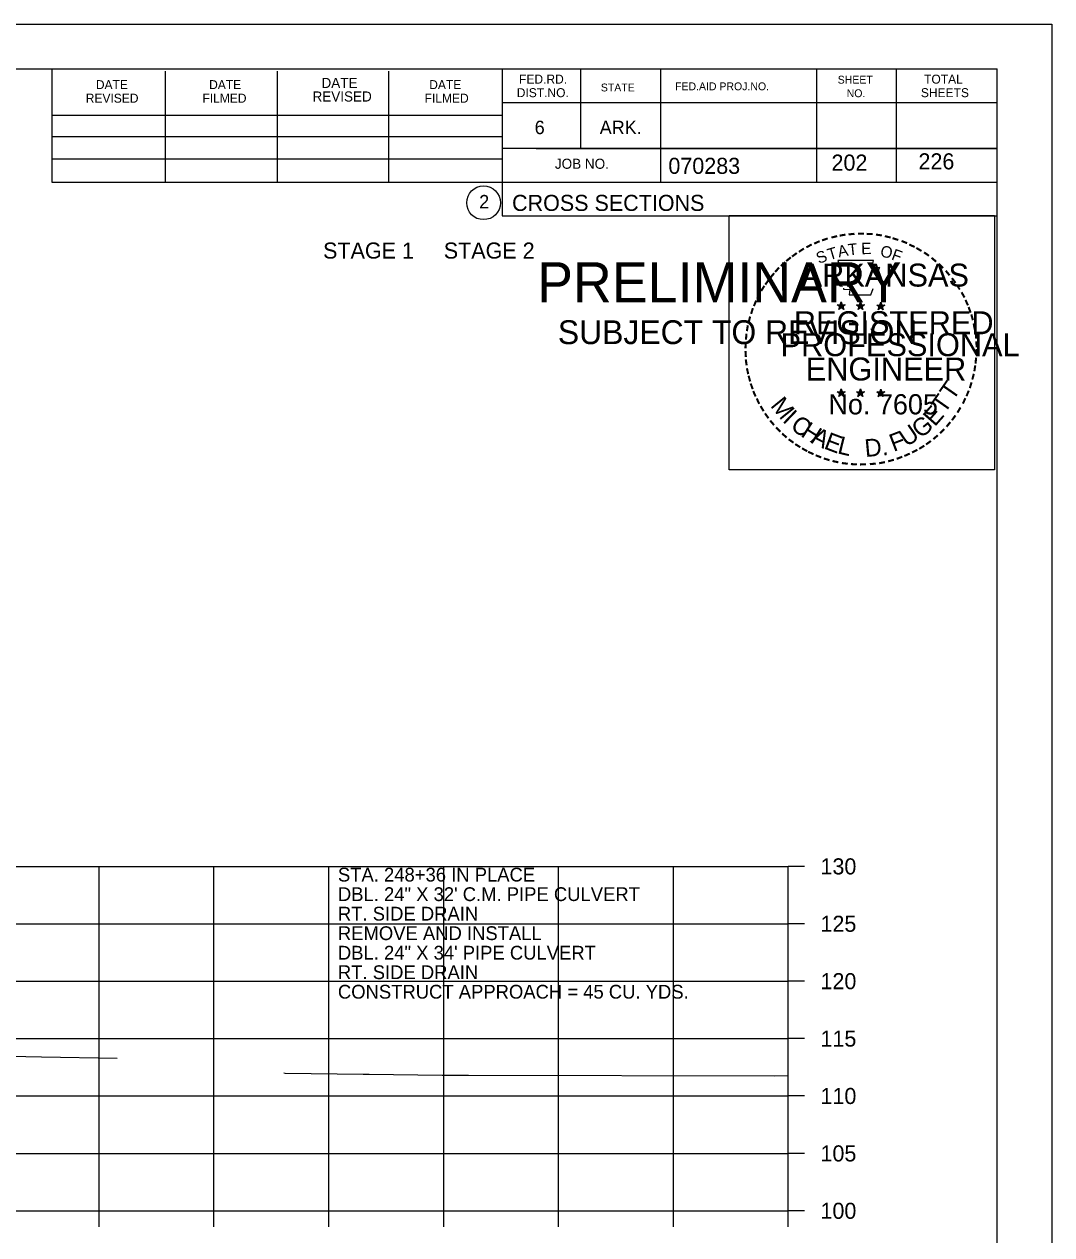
# Model space of a CAD drawing. Extents: x 1175611 to 1176402, y -433344 to -416213.
# Drawn here: x 1175854.5 to 1175943.9, y -421502 to -421396.6 of the extents above; entities that cross this region are included whole.
import ezdxf

# ---------------------------------------------------------------- set-up
doc = ezdxf.new("R2010")
doc.units = 0
for name, color, linetype in [('Default', 7, 'Continuous'), ('R_Axis', 7, 'Continuous'), ('R_Axis Annot', 7, 'Continuous'), ('R_Border', 7, 'Continuous'), ('R_Border Notes', 7, 'Continuous'), ('R_Border PE', 7, 'Continuous'), ('R_Border Prem', 7, 'Continuous'), ('R_Exist Surface', 7, 'Continuous'), ('R_Grid', 7, 'Continuous'), ('R_No Plot', 7, 'Continuous'), ('R_Water Annot', 7, 'Continuous')]:
    doc.layers.add(name, color=color, linetype=linetype)

msp = doc.modelspace()

# ---------------------------------------------------------------- linework, layer by layer
at = {"layer": 'R_Axis'}
for p, q in [((1175920.97, -421499.96), (1175920.97, -421469.96)), ((1175922.37, -421469.96), (1175920.97, -421469.96)), ((1175922.37, -421474.96), (1175920.97, -421474.96)), ((1175922.37, -421479.96), (1175920.97, -421479.96)), ((1175922.37, -421484.96), (1175920.97, -421484.96)), ((1175922.37, -421489.96), (1175920.97, -421489.96)), ((1175922.37, -421494.96), (1175920.97, -421494.96)), ((1175640.97, -421499.96), (1175920.97, -421499.96)), ((1175860.97, -421501.36), (1175860.97, -421499.96)), ((1175870.97, -421501.36), (1175870.97, -421499.96)), ((1175880.97, -421501.36), (1175880.97, -421499.96)), ((1175890.97, -421501.36), (1175890.97, -421499.96)), ((1175900.97, -421501.36), (1175900.97, -421499.96)), ((1175910.97, -421501.36), (1175910.97, -421499.96)), ((1175920.97, -421501.36), (1175920.97, -421499.96)), ((1175922.37, -421499.96), (1175920.97, -421499.96))]:
    msp.add_line(p, q, dxfattribs=at)
at = {"layer": 'R_Border'}
for p, q in [((1175622.97, -421400.5), (1175939.15, -421400.5)), ((1175856.89, -421410.38), (1175856.89, -421400.5)), ((1175866.75, -421410.38), (1175866.75, -421400.7)), ((1175876.51, -421410.38), (1175876.51, -421400.7)), ((1175886.19, -421410.38), (1175886.19, -421400.7)), ((1175896.05, -421400.5), (1175896.05, -421413.3)), ((1175902.89, -421400.5), (1175902.89, -421407.44)), ((1175909.83, -421400.5), (1175909.83, -421410.38)), ((1175923.41, -421400.5), (1175923.41, -421410.38)), ((1175930.35, -421400.5), (1175930.35, -421410.38)), ((1175939.15, -421605.96), (1175939.15, -421400.5)), ((1175939.15, -421403.44), (1175896.05, -421403.44)), ((1175939.15, -421403.42), (1175939.15, -421403.42)), ((1175856.89, -421404.52), (1175896.05, -421404.52)), ((1175856.89, -421406.38), (1175896.05, -421406.38)), ((1175939.15, -421407.44), (1175896.05, -421407.44)), ((1175899.01, -421407.44), (1175939.15, -421407.44)), ((1175856.89, -421410.38), (1175856.89, -421408.32)), ((1175856.89, -421408.32), (1175896.05, -421408.32)), ((1175939.15, -421410.38), (1175856.89, -421410.38)), ((1175896.05, -421413.3), (1175939.15, -421413.3))]:
    msp.add_line(p, q, dxfattribs=at)
msp.add_circle((1175894.44, -421412.16), 1.47, dxfattribs=at)
at = {"layer": 'R_Border PE'}
for p, q in [((1175925.23, -421421.05), (1175925.58, -421421.16)), ((1175925.23, -421421.05), (1175925.49, -421421.1)), ((1175925.23, -421421.05), (1175925.47, -421421.18)), ((1175925.37, -421421.46), (1175925.58, -421421.16)), ((1175925.37, -421421.46), (1175925.49, -421421.22)), ((1175925.37, -421421.46), (1175925.58, -421421.24)), ((1175925.58, -421420.8), (1175925.54, -421421.05)), ((1175925.58, -421421.16), (1175925.58, -421420.8)), ((1175925.58, -421420.8), (1175925.63, -421421.05)), ((1175925.93, -421421.05), (1175925.58, -421421.16)), ((1175925.8, -421421.46), (1175925.58, -421421.16)), ((1175925.8, -421421.46), (1175925.58, -421421.25)), ((1175925.93, -421421.05), (1175925.64, -421421.1)), ((1175925.8, -421421.46), (1175925.66, -421421.17)), ((1175925.93, -421421.05), (1175925.73, -421421.16)), ((1175926.9, -421421.05), (1175927.25, -421421.16)), ((1175926.9, -421421.05), (1175927.16, -421421.1)), ((1175926.9, -421421.05), (1175927.14, -421421.18)), ((1175927.04, -421421.46), (1175927.25, -421421.16)), ((1175927.04, -421421.46), (1175927.16, -421421.22)), ((1175927.04, -421421.46), (1175927.25, -421421.24)), ((1175927.25, -421420.8), (1175927.21, -421421.05)), ((1175927.25, -421421.16), (1175927.25, -421420.8)), ((1175927.25, -421420.8), (1175927.3, -421421.05)), ((1175927.6, -421421.05), (1175927.25, -421421.16)), ((1175927.47, -421421.46), (1175927.25, -421421.16)), ((1175927.47, -421421.46), (1175927.25, -421421.25)), ((1175927.6, -421421.05), (1175927.31, -421421.1)), ((1175927.47, -421421.46), (1175927.33, -421421.17)), ((1175927.6, -421421.05), (1175927.4, -421421.16)), ((1175928.67, -421421.07), (1175929.02, -421421.18)), ((1175928.67, -421421.07), (1175928.92, -421421.11)), ((1175928.67, -421421.07), (1175928.91, -421421.19)), ((1175928.8, -421421.47), (1175929.02, -421421.18)), ((1175928.8, -421421.47), (1175928.93, -421421.23)), ((1175928.8, -421421.47), (1175929.02, -421421.26)), ((1175929.02, -421420.81), (1175928.98, -421421.06)), ((1175929.02, -421421.18), (1175929.02, -421420.81)), ((1175929.02, -421420.81), (1175929.07, -421421.06)), ((1175929.36, -421421.07), (1175929.02, -421421.18)), ((1175929.23, -421421.47), (1175929.02, -421421.18)), ((1175929.23, -421421.47), (1175929.02, -421421.26)), ((1175929.36, -421421.07), (1175929.08, -421421.11)), ((1175929.23, -421421.47), (1175929.09, -421421.18)), ((1175929.36, -421421.07), (1175929.16, -421421.17)), ((1175925.23, -421428.63), (1175925.58, -421428.74)), ((1175925.23, -421428.63), (1175925.48, -421428.67)), ((1175925.23, -421428.63), (1175925.47, -421428.75)), ((1175925.36, -421429.03), (1175925.58, -421428.74)), ((1175925.36, -421429.03), (1175925.49, -421428.79)), ((1175925.36, -421429.03), (1175925.58, -421428.82)), ((1175925.58, -421428.37), (1175925.54, -421428.62)), ((1175925.58, -421428.74), (1175925.58, -421428.37)), ((1175925.58, -421428.37), (1175925.63, -421428.62)), ((1175925.93, -421428.63), (1175925.58, -421428.74)), ((1175925.79, -421429.03), (1175925.58, -421428.74)), ((1175925.79, -421429.03), (1175925.58, -421428.82)), ((1175925.93, -421428.63), (1175925.64, -421428.68)), ((1175925.79, -421429.03), (1175925.66, -421428.74)), ((1175925.93, -421428.63), (1175925.72, -421428.73)), ((1175926.9, -421428.63), (1175927.25, -421428.74)), ((1175926.9, -421428.63), (1175927.15, -421428.67)), ((1175926.9, -421428.63), (1175927.14, -421428.75)), ((1175927.03, -421429.03), (1175927.25, -421428.74)), ((1175927.03, -421429.03), (1175927.16, -421428.79)), ((1175927.03, -421429.03), (1175927.25, -421428.82)), ((1175927.25, -421428.37), (1175927.21, -421428.62)), ((1175927.25, -421428.74), (1175927.25, -421428.37)), ((1175927.25, -421428.37), (1175927.3, -421428.62)), ((1175927.6, -421428.63), (1175927.25, -421428.74)), ((1175927.46, -421429.03), (1175927.25, -421428.74)), ((1175927.46, -421429.03), (1175927.25, -421428.82)), ((1175927.6, -421428.63), (1175927.31, -421428.68)), ((1175927.46, -421429.03), (1175927.32, -421428.74)), ((1175927.6, -421428.63), (1175927.39, -421428.73)), ((1175928.67, -421428.64), (1175929.02, -421428.75)), ((1175928.67, -421428.64), (1175928.92, -421428.68)), ((1175928.67, -421428.64), (1175928.9, -421428.76)), ((1175928.8, -421429.04), (1175929.02, -421428.75)), ((1175928.8, -421429.04), (1175928.93, -421428.8)), ((1175928.8, -421429.04), (1175929.01, -421428.83)), ((1175929.02, -421428.38), (1175928.97, -421428.63)), ((1175929.23, -421429.04), (1175929.01, -421428.83)), ((1175929.02, -421428.75), (1175929.02, -421428.38)), ((1175929.02, -421428.38), (1175929.06, -421428.63)), ((1175929.36, -421428.64), (1175929.02, -421428.75)), ((1175929.23, -421429.04), (1175929.02, -421428.75)), ((1175929.36, -421428.64), (1175929.08, -421428.69)), ((1175929.23, -421429.04), (1175929.09, -421428.75)), ((1175929.36, -421428.64), (1175929.16, -421428.74))]:
    msp.add_line(p, q, dxfattribs=at)
for points in [[(1175925.28, -421417.18), (1175925.54, -421418)], [(1175928.79, -421418.1), (1175928.93, -421417.81), (1175928.24, -421417.84), (1175928.39, -421417.18), (1175925.28, -421417.18)], [(1175925.77, -421419.6), (1175925.77, -421419.69), (1175926.33, -421419.7), (1175926.28, -421420.18), (1175928.15, -421420.18), (1175928.35, -421419.64)], [(1175925.58, -421420.8), (1175925.8, -421421.46), (1175925.23, -421421.05), (1175925.93, -421421.05), (1175925.37, -421421.46), (1175925.58, -421420.8)], [(1175927.25, -421420.8), (1175927.47, -421421.46), (1175926.9, -421421.05), (1175927.6, -421421.05), (1175927.04, -421421.46), (1175927.25, -421420.8)], [(1175929.02, -421420.81), (1175929.23, -421421.47), (1175928.67, -421421.07), (1175929.36, -421421.07), (1175928.8, -421421.47), (1175929.02, -421420.81)], [(1175925.58, -421428.37), (1175925.79, -421429.03), (1175925.23, -421428.63), (1175925.93, -421428.63), (1175925.36, -421429.03), (1175925.58, -421428.37)], [(1175927.25, -421428.37), (1175927.46, -421429.03), (1175926.9, -421428.63), (1175927.6, -421428.63), (1175927.03, -421429.03), (1175927.25, -421428.37)], [(1175929.02, -421428.38), (1175929.23, -421429.04), (1175928.67, -421428.64), (1175929.36, -421428.64), (1175928.8, -421429.04), (1175929.02, -421428.38)]]:
    msp.add_lwpolyline(points, dxfattribs=at)
for centre, radius in [((1175925.58, -421421.17), 0.172), ((1175925.58, -421421.17), 0.145), ((1175925.58, -421421.17), 0.116), ((1175925.58, -421421.17), 0.0991), ((1175925.58, -421421.17), 0.0747), ((1175925.58, -421421.17), 0.0495), ((1175925.58, -421421.17), 0.0296), ((1175927.25, -421421.17), 0.172), ((1175927.25, -421421.17), 0.145), ((1175927.25, -421421.17), 0.116), ((1175927.25, -421421.17), 0.0991), ((1175927.25, -421421.17), 0.0747), ((1175927.25, -421421.17), 0.0495), ((1175927.25, -421421.17), 0.0296), ((1175929.02, -421421.18), 0.172), ((1175929.02, -421421.18), 0.145), ((1175929.02, -421421.18), 0.116), ((1175929.02, -421421.18), 0.0991), ((1175929.02, -421421.18), 0.0747), ((1175929.02, -421421.18), 0.0495), ((1175929.02, -421421.18), 0.0296), ((1175925.58, -421428.74), 0.172), ((1175925.58, -421428.74), 0.145), ((1175925.58, -421428.74), 0.116), ((1175925.58, -421428.74), 0.0991), ((1175925.58, -421428.74), 0.0747), ((1175925.58, -421428.74), 0.0495), ((1175925.58, -421428.74), 0.0296), ((1175927.25, -421428.74), 0.172), ((1175927.25, -421428.74), 0.145), ((1175927.25, -421428.74), 0.116), ((1175927.25, -421428.74), 0.0991), ((1175927.25, -421428.74), 0.0747), ((1175927.25, -421428.74), 0.0495), ((1175927.25, -421428.74), 0.0296), ((1175929.01, -421428.75), 0.172), ((1175929.01, -421428.75), 0.145), ((1175929.01, -421428.75), 0.116), ((1175929.01, -421428.75), 0.0991), ((1175929.01, -421428.75), 0.0747), ((1175929.01, -421428.75), 0.0495), ((1175929.01, -421428.75), 0.0296)]:
    msp.add_circle(centre, radius, dxfattribs=at)
at = {"layer": 'R_Exist Surface'}
for points in [[(1175847.72, -421486.38), (1175855.95, -421486.56), (1175862.55, -421486.68)], [(1175877.04, -421487.95), (1175877.17, -421487.96), (1175883.96, -421488.07), (1175884.49, -421488.07), (1175890.84, -421488.15), (1175893.14, -421488.15), (1175919.81, -421488.2), (1175920.97, -421488.18)]]:
    msp.add_lwpolyline(points, dxfattribs=at)
at = {"layer": 'R_Grid'}
for p, q in [((1175640.97, -421469.96), (1175920.97, -421469.96)), ((1175640.97, -421469.96), (1175920.97, -421469.96)), ((1175860.97, -421499.96), (1175860.97, -421469.96)), ((1175860.97, -421499.96), (1175860.97, -421469.96)), ((1175870.97, -421499.96), (1175870.97, -421469.96)), ((1175870.97, -421499.96), (1175870.97, -421469.96)), ((1175880.97, -421499.96), (1175880.97, -421469.96)), ((1175880.97, -421499.96), (1175880.97, -421469.96)), ((1175890.97, -421499.96), (1175890.97, -421469.96)), ((1175890.97, -421499.96), (1175890.97, -421469.96)), ((1175900.97, -421499.96), (1175900.97, -421469.96)), ((1175900.97, -421499.96), (1175900.97, -421469.96)), ((1175910.97, -421499.96), (1175910.97, -421469.96)), ((1175910.97, -421499.96), (1175910.97, -421469.96)), ((1175920.97, -421499.96), (1175920.97, -421469.96)), ((1175920.97, -421499.96), (1175920.97, -421469.96)), ((1175640.97, -421474.96), (1175920.97, -421474.96)), ((1175640.97, -421474.96), (1175920.97, -421474.96)), ((1175640.97, -421479.96), (1175920.97, -421479.96)), ((1175640.97, -421479.96), (1175920.97, -421479.96)), ((1175640.97, -421484.96), (1175920.97, -421484.96)), ((1175640.97, -421484.96), (1175920.97, -421484.96)), ((1175640.97, -421489.96), (1175920.97, -421489.96)), ((1175640.97, -421489.96), (1175920.97, -421489.96)), ((1175640.97, -421494.96), (1175920.97, -421494.96)), ((1175640.97, -421494.96), (1175920.97, -421494.96)), ((1175640.97, -421499.96), (1175920.97, -421499.96)), ((1175640.97, -421499.96), (1175920.97, -421499.96))]:
    msp.add_line(p, q, dxfattribs=at)
at = {"layer": 'R_No Plot'}
msp.add_line((1175610.57, -421396.61), (1175943.91, -421396.61), dxfattribs=at)
for points in [[(1175610.57, -421396.61), (1175943.91, -421396.61), (1175943.91, -421609.94), (1175610.57, -421609.94)], [(1175915.82, -421413.27), (1175938.92, -421413.27), (1175938.92, -421435.42), (1175915.82, -421435.42)]]:
    msp.add_lwpolyline(points, close=True, dxfattribs=at)

# ---------------------------------------------------------------- texts
at = {"layer": 'Default'}
msp.add_text('STAGE 1     STAGE 2', height=1.4, dxfattribs=at).set_placement((1175880.47, -421417.02))
at = {"layer": 'R_Axis Annot'}
for s, p in [('130', (1175923.77, -421470.66)), ('125', (1175923.77, -421475.66)), ('120', (1175923.77, -421480.66)), ('115', (1175923.77, -421485.66)), ('110', (1175923.77, -421490.66)), ('105', (1175923.77, -421495.66)), ('100', (1175923.77, -421500.66))]:
    msp.add_text(s, height=1.4, dxfattribs=at).set_placement(p)
at = {"layer": 'R_Border'}
for s, height, p in [('DATE', 0.782, (1175860.69, -421402.26)), ('DATE', 0.782, (1175870.55, -421402.26)), ('DATE', 0.879, (1175880.33, -421402.16)), ('DATE', 0.782, (1175889.71, -421402.26)), ('FED.RD.', 0.782, (1175897.53, -421401.78)), ('SHEET', 0.684, (1175925.27, -421401.78)), ('TOTAL', 0.782, (1175932.79, -421401.78)), ('REVISED', 0.879, (1175879.55, -421403.34)), ('DIST.NO.', 0.782, (1175897.33, -421402.96)), ('STATE', 0.684, (1175904.65, -421402.46)), ('FED.AID PROJ.NO.', 0.684, (1175911.11, -421402.36)), ('NO.', 0.684, (1175926.05, -421402.96)), ('SHEETS', 0.782, (1175932.51, -421402.96)), ('REVISED', 0.782, (1175859.81, -421403.44)), ('FILMED', 0.782, (1175869.97, -421403.44)), ('FILMED', 0.782, (1175889.31, -421403.44)), ('6', 1.17, (1175898.89, -421406.18)), ('ARK.', 1.172, (1175904.55, -421406.18)), ('JOB NO.', 0.879, (1175900.65, -421409.2)), ('070283', 1.4, (1175910.53, -421409.64)), ('2', 1.17, (1175894.06, -421412.65)), ('CROSS SECTIONS', 1.4, (1175896.92, -421412.87))]:
    msp.add_text(s, height=height, rotation=360, dxfattribs=at).set_placement(p)
at = {"layer": 'R_Border Notes'}
for s, p in [('226', (1175932.3, -421409.25)), ('202', (1175924.73, -421409.36))]:
    msp.add_text(s, height=1.4, dxfattribs=at).set_placement(p)
at = {"layer": 'R_Border PE'}
for s, height, rotation, p in [('-', 1.6, 19.1761, (1175924.02, -421416.05)), ('-', 1.6, 13.6301, (1175924.77, -421415.81)), ('-', 1.6, 10.2193, (1175925.45, -421415.65)), ('-', 1.6, 5.8968, (1175926.18, -421415.54)), ('-', 1.6, 0.1862, (1175926.95, -421415.46)), ('-', 1.6, 357.743, (1175927.67, -421415.48)), ('-', 1.6, 352.1617, (1175928.42, -421415.53)), ('-', 1.6, 347.2049, (1175929.14, -421415.65)), ('-', 1.6, 342.3362, (1175929.77, -421415.8)), ('-', 1.6, 34.0636, (1175922.16, -421417)), ('-', 1.6, 28.7918, (1175922.76, -421416.63)), ('-', 1.6, 24.3072, (1175923.39, -421416.32)), ('T', 1, 16.4036, (1175924.54, -421417.17)), ('A', 1, 11.2132, (1175925.37, -421416.92)), ('T', 1, 6.0228, (1175926.22, -421416.75)), ('E', 1, 0.8323, (1175927.32, -421416.64)), ('O', 1, 350.4515, (1175928.93, -421416.85)), ('F', 1, 340.0707, (1175929.88, -421417.08)), ('-', 1.6, 337.8551, (1175930.51, -421416.02)), ('-', 1.6, 334.1211, (1175931.14, -421416.3)), ('-', 1.6, 329.6409, (1175931.72, -421416.58)), ('-', 1.6, 42.9622, (1175920.67, -421418.19)), ('-', 1.6, 38.9507, (1175921.1, -421417.78)), ('-', 1.6, 36.2317, (1175921.58, -421417.4)), ('S', 1, 21.594, (1175923.63, -421417.5)), ('-', 1.6, 325.8627, (1175932.36, -421416.94)), ('-', 1.6, 320.5297, (1175932.97, -421417.37)), ('-', 1.6, 50.6142, (1175919.82, -421419.16)), ('-', 1.6, 48.423, (1175920.22, -421418.67)), ('ARKANSAS', 2, 360, (1175922.13, -421419.46)), ('-', 1.6, 315.5786, (1175933.57, -421417.85)), ('-', 1.6, 309.8797, (1175934.14, -421418.4)), ('-', 1.6, 58.0706, (1175919.08, -421420.25)), ('-', 1.6, 54.2325, (1175919.41, -421419.73)), ('-', 1.6, 306.6522, (1175934.66, -421419.01)), ('-', 1.4, 303.6753, (1175935.15, -421419.57)), ('-', 1.6, 62.8713, (1175918.77, -421420.87)), ('-', 1.6, 299.6684, (1175935.47, -421420.18)), ('-', 1.6, 72.3945, (1175918.29, -421422.11)), ('-', 1.6, 67.7743, (1175918.51, -421421.48)), ('DWB', 0.01, 360, (1175925.57, -421421.17)), ('DWB', 0.01, 360, (1175927.24, -421421.17)), ('DWB', 0.01, 360, (1175929, -421421.18)), ('-', 1.6, 294.6628, (1175935.79, -421420.79)), ('-', 1.6, 290.5728, (1175936.05, -421421.37)), ('-', 1.6, 75.461, (1175918.09, -421422.82)), ('REGISTERED', 2, 360, (1175921.45, -421423.61)), ('-', 1.6, 285.1233, (1175936.28, -421421.95)), ('-', 1.6, 85.1863, (1175917.89, -421424.23)), ('-', 1.6, 81.2013, (1175917.96, -421423.53)), ('PROFESSIONAL', 2, 360, (1175920.3, -421425.52)), ('-', 1.6, 280.5493, (1175936.48, -421422.69)), ('-', 1.6, 276.5962, (1175936.65, -421423.46)), ('-', 1.6, 89.0622, (1175917.86, -421424.93)), ('-', 1.6, 274.3301, (1175936.71, -421424.18)), ('-', 1.6, 94.1959, (1175917.9, -421425.65)), ('ENGINEER', 2, 360, (1175922.49, -421427.64)), ('-', 1.6, 263.5172, (1175936.72, -421425.48)), ('-', 1.6, 269.9407, (1175936.74, -421424.81)), ('-', 1.6, 98.9479, (1175917.97, -421426.32)), ('-', 1.6, 101.7149, (1175918.1, -421427.05)), ('-', 1.6, 260.9953, (1175936.65, -421426.13)), ('-', 1.6, 105.4578, (1175918.27, -421427.65)), ('-', 1.6, 109.0874, (1175918.48, -421428.28)), ('T', 1.54, 55.055, (1175935.3, -421429.47)), ('-', 1.6, 252.8681, (1175936.36, -421427.53)), ('-', 1.6, 255.7626, (1175936.54, -421426.81)), ('-', 1.6, 114.0643, (1175918.73, -421428.87)), ('No. 7605', 1.757, 360, (1175924.46, -421430.59)), ('DWB', 0.01, 360, (1175925.56, -421428.74)), ('DWB', 0.01, 360, (1175927.23, -421428.74)), ('DWB', 0.01, 360, (1175929, -421428.75)), ('T', 1.54, 55.055, (1175934.57, -421430.59)), ('-', 1.6, 247.8887, (1175936.14, -421428.2)), ('-', 1.6, 115.7289, (1175919.04, -421429.49)), ('-', 1.6, 120.4471, (1175919.4, -421430.08)), ('M', 1.54, 308.9175, (1175919.35, -421429.85)), ('E', 1.54, 48.7313, (1175933.72, -421431.72)), ('-', 1.6, 239.0712, (1175935.48, -421429.59)), ('-', 1.6, 244.6197, (1175935.87, -421428.83)), ('-', 1.6, 125.8934, (1175919.8, -421430.64)), ('I', 1.54, 316.4636, (1175920.39, -421431.17)), ('C', 1.54, 324.0197, (1175921.06, -421431.79)), ('G', 1.54, 38.2173, (1175932.47, -421432.74)), ('-', 1.6, 233.8452, (1175935.08, -421430.24)), ('-', 1.6, 130.7181, (1175920.26, -421431.19)), ('-', 1.6, 134.2238, (1175920.78, -421431.74)), ('H', 1.54, 327.5342, (1175921.97, -421432.45)), ('A', 1.54, 332.5513, (1175922.83, -421432.98)), ('F', 1.54, 20.8202, (1175930.13, -421433.87)), ('U', 1.54, 34.4052, (1175931.27, -421433.47)), ('-', 1.6, 225.7653, (1175934.17, -421431.37)), ('-', 1.6, 231.2538, (1175934.65, -421430.8)), ('-', 1.6, 138.9338, (1175921.3, -421432.2)), ('-', 1.6, 144.6463, (1175921.86, -421432.61)), ('-', 1.6, 148.0898, (1175922.42, -421432.98)), ('E', 1.54, 339.2068, (1175923.99, -421433.54)), ('L', 1.54, 346.2929, (1175925.18, -421433.97)), ('D.', 1.54, 5.2602, (1175927.68, -421434.31)), ('-', 1.6, 215.7363, (1175933.1, -421432.35)), ('-', 1.6, 221.0851, (1175933.65, -421431.88)), ('-', 1.6, 151.5704, (1175923, -421433.3)), ('-', 1.6, 154.6002, (1175923.52, -421433.55)), ('-', 1.6, 158.5612, (1175924.15, -421433.8)), ('-', 1.6, 200.7184, (1175930.76, -421433.67)), ('-', 1.6, 204.2516, (1175931.38, -421433.4)), ('-', 1.6, 207.3568, (1175932.01, -421433.08)), ('-', 1.6, 212.2491, (1175932.56, -421432.74)), ('-', 1.6, 162.7983, (1175924.83, -421434.02)), ('-', 1.6, 167.5555, (1175925.55, -421434.18)), ('-', 1.6, 173.1155, (1175926.32, -421434.29)), ('-', 1.6, 176.5183, (1175927.07, -421434.34)), ('-', 1.6, 181.5918, (1175927.81, -421434.32)), ('-', 1.6, 185.8167, (1175928.62, -421434.25)), ('-', 1.6, 191.2858, (1175929.36, -421434.12)), ('-', 1.6, 195.4743, (1175930.09, -421433.92))]:
    msp.add_text(s, height=height, rotation=rotation, dxfattribs=at).set_placement(p)
at = {"layer": 'R_Border Prem'}
for s, height, p in [('PRELIMINARY', 3.5, (1175899.1, -421420.84)), ('DWB', 0.01, (1175899.85, -421418.99)), ('SUBJECT TO REVISION', 2.0751, (1175900.91, -421424.47))]:
    msp.add_text(s, height=height, rotation=360, dxfattribs=at).set_placement(p)
at = {"layer": 'R_Water Annot'}
for s, p in [('STA. 248+36 IN PLACE', (1175881.76, -421471.28)), ('DBL. 24" X 32\' C.M. PIPE CULVERT', (1175881.76, -421472.98)), ('RT. SIDE DRAIN', (1175881.76, -421474.68)), ('REMOVE AND INSTALL', (1175881.76, -421476.38)), ('DBL. 24" X 34\' PIPE CULVERT', (1175881.76, -421478.08)), ('RT. SIDE DRAIN ', (1175881.76, -421479.78)), ('CONSTRUCT APPROACH = 45 CU. YDS.', (1175881.76, -421481.48))]:
    msp.add_text(s, height=1.2, dxfattribs=at).set_placement(p)

doc.saveas('drawing.dxf')
